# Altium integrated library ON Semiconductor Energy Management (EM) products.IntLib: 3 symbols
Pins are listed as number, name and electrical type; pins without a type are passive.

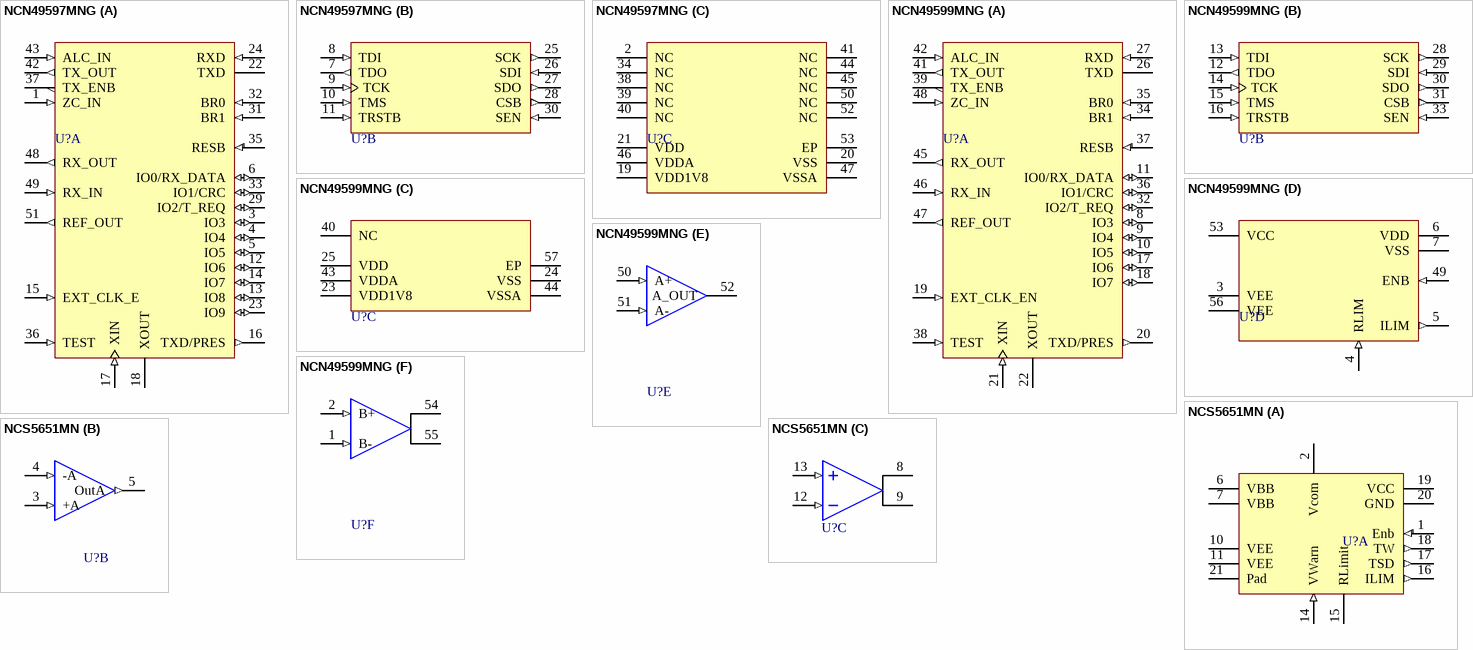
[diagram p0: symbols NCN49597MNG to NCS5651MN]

## NCN49597MNG
designator U?, comment NCN49597  (value not drawn)
Power Line Carrier Modem, 3 to 3.6 V, -40 to 115 degC, Pb-Free; Manufacturer: ON Semiconductor; PartNumber: NCN49597MNG; Data Transmission Standard: S-FSK; Number of Drivers: 1; Packing: Tube; VCC Max (V): 3.6; VCC Min (V): 3
footprint 485M_L
footprint 485M_M
footprint 485M_N
part A pins: 1 ZC_IN (in) "50/60 Hz input for mains zero cross detection", 3 IO3 (io) "General Purpose I/O’s", 4 IO4 (io) "General Purpose I/O’s", 5 IO5 (io) "General Purpose I/O’s", 6 IO0/RX_DATA (io) "Data reception indication (in ROM mode)", 12 IO6 (io) "General Purpose I/O’s", 13 IO8 (io) "General Purpose I/O’s", 14 IO7 (io) "General Purpose I/O’s", 15 EXT_CLK_E (in) "External Clock Enable input", 16 TXD/PRES (out) "Output of transmitted data (TXD) or PRE_SLOT signal (PRES)", 17 XIN (in) "Xtal input (can be driven by an internal clock)", 18 XOUT "Xtal output (output floating when XIN driven by external clock)", 22 TXD (oc) "SCI transmit output", 23 IO9 (io) "General Purpose I/O’s", 24 RXD (in) "SCI receive input (Schmitt trigger input)", 29 IO2/T_REQ (io) "Transmit Request input (in ROM mode)", 31 BR1 (in) "SCI baud rate selection", 32 BR0 (in) "SCI baud rate selection", 33 IO1/CRC (io) "Correct frame CRC indication (in ROM mode)", 35 RESB (in) "Master reset bar (Schmitt trigger input, active low)", 36 TEST (in) "Hardware Test enable (Schmitt trigger input)", 37 TX_ENB (oc) "TX enable (active low)", 42 TX_OUT (out) "Transmitter output", 43 ALC_IN (in) "Automatic level control input", 48 RX_OUT (out) "Output of receiver low noise operational amplifier", 49 RX_IN (in) "Positive input of receiver low noise operational amplifier", 51 REF_OUT (out) "Reference output for stabilization"
part B pins: 7 TDO (out) "Test data output", 8 TDI (in) "Test data input", 9 TCK (in) "Test clock", 10 TMS (in) "Test mode select", 11 TRSTB (in) "Test reset bar (active low)", 25 SCK (out) "SPI interface external Flash", 26 SDI (in) "SPI interface external Flash (Schmitt trigger input)", 27 SDO (out) "SPI interface external Flash", 28 CSB (out) "SPI interface external Flash (Schmitt trigger input)", 30 SEN (in) "SPI interface Enable external Flash"
part C pins: 2 NC "Pins 2, 34, 38..41, 44, 45, 50, 52 are not connected. These pins need to be left open or connected to the GND plane.", 19 VDD1V8 (power) "1V8 regulator output. Foresee a decoupling capacitor", 20 VSS (power) "Digital ground", 21 VDD (power) "3.3V digital supply", 34 NC "Pins 2, 34, 38..41, 44, 45, 50, 52 are not connected. These pins need to be left open or connected to the GND plane.", 38 NC "Pins 2, 34, 38..41, 44, 45, 50, 52 are not connected. These pins need to be left open or connected to the GND plane.", 39 NC "Pins 2, 34, 38..41, 44, 45, 50, 52 are not connected. These pins need to be left open or connected to the GND plane.", 40 NC "Pins 2, 34, 38..41, 44, 45, 50, 52 are not connected. These pins need to be left open or connected to the GND plane.", 41 NC "Pins 2, 34, 38..41, 44, 45, 50, 52 are not connected. These pins need to be left open or connected to the GND plane.", 44 NC "Pins 2, 34, 38..41, 44, 45, 50, 52 are not connected. These pins need to be left open or connected to the GND plane.", 45 NC "Pins 2, 34, 38..41, 44, 45, 50, 52 are not connected. These pins need to be left open or connected to the GND plane.", 46 VDDA (power) "3.3V analog supply", 47 VSSA (power) "Analog ground", 50 NC "Pins 2, 34, 38..41, 44, 45, 50, 52 are not connected. These pins need to be left open or connected to the GND plane.", 52 NC "Pins 2, 34, 38..41, 44, 45, 50, 52 are not connected. These pins need to be left open or connected to the GND plane.", 53 EP

## NCN49599MNG
designator U?, comment NCN49599  (value not drawn)
Power Line Carrier Modem, 3 to 3.6 V, -40 to 85 degC, Pb-Free; Manufacturer: ON Semiconductor; PartNumber: NCN49599MNG; Data Transmission Standard: S-FSK; Number of Drivers: 1; Packing: Tube
footprint 485CN_N
footprint 485CN_L
footprint 485CN_M
part A pins: 8 IO3 (io) "General Purpose I/O?", 9 IO4 (io) "General Purpose I/O?", 10 IO5 (io) "General Purpose I/O?", 11 IO0/RX_DATA (io) "General Purpose I/O?", 17 IO6 (io) "General Purpose I/O?", 18 IO7 (io) "General Purpose I/O?", 19 EXT_CLK_EN (in) "External Clock Enable input", 20 TXD/PRES (out) "Output of transmitted data (TXD) or PRE_SLOT signal (PRES)", 21 XIN (in) "Xtal input (can be driven by an external clock)", 22 XOUT "Xtal output (output floating when XIN driven by external (clock)", 26 TXD (oc) "SCI transmit output", 27 RXD (in) "SCI receive input (Schmitt trigger input)", 32 IO2/T_REQ (io) "General Purpose I/O?", 34 BR1 (in) "SCI baud rate selection", 35 BR0 (in) "SCI baud rate selection", 36 IO1/CRC (io) "General Purpose I/O?", 37 RESB (in) "Master reset bar (Schmitt trigger input, active low)", 38 TEST (in) "Hardware Test enable (Schmitt trigger input)", 39 TX_ENB (oc) "TX enable (active low)", 41 TX_OUT (out) "Transmitter output", 42 ALC_IN (in) "Automatic level control input", 45 RX_OUT (out) "Output of receiver low noise operational amplifier", 46 RX_IN (in) "Positive input of receiver low noise operational amplifier", 47 REF_OUT (out) "Reference output for stabilization", 48 ZC_IN (in) "50/60 Hz input for mains zero cross detection"
part B pins: 12 TDO (out) "Test data output", 13 TDI (in) "Test data input", 14 TCK (in) "Test clock", 15 TMS (in) "Test mode select", 16 TRSTB (in) "Test reset bar (active low)", 28 SCK (out) "SPI interface external Flash", 29 SDI (in) "SPI interface external Flash (Schmitt trigger input)", 30 SDO (out) "SPI interface external Flash", 31 CSB (out) "SPI interface external Flash (Schmitt trigger input)", 33 SEN (in) "SPI interface Enable external Flash"
part C pins: 23 VDD1V8 (power) "1V8 regulator output. Foresee a decoupling capacitor", 24 VSS (power) "Digital ground", 25 VDD (power) "3.3V digital supply", 40 NC "Not connected pin. Tie to GND.", 43 VDDA (power) "3.3V analog supply", 44 VSSA (power) "Analog ground", 57 EP
part D pins: 3 VEE (power) "Negative supply for power amplifiers A and B", 4 RLIM (in) "Output B current limit set resistor", 5 ILIM (out) "Current limit logic flag", 6 VDD (power) "3.3V digital supply", 7 VSS (power) "Digital ground", 49 ENB (in) "Enable / shutdown power amplifier (active low)", 53 VCC (power) "Positive supply for power amplifiers A and B", 56 VEE (power) "Negative supply for power amplifiers A and B"
part E pins: 50 A+ (in) "Positive (+) input of operational amplifier A", 51 A- (in) "Negative (-) input of operational amplifier A", 52 A_OUT (hiz) "Output of operational amplifier A"
part F pins: 1 B- (in) "Negative (-) input of operational amplifier B", 2 B+ (in) "Positive (+) input of operational amplifier B", 54 B_OUT1 (hiz) "Output of operational amplifier B", 55 B_OUT2 (hiz) "Output of operational amplifier B"

## NCS5651MN
designator U?, comment NCS5651  (value not drawn)
2 amp PLC line driver; Manufacturer: ON Semiconductor; Part: NCS5651MN
footprint 485E-01-L
footprint 485E-01-M
footprint 485E-01-N
part A pins: 1 Enb (in), 2 Vcom (power), 6 VBB (power), 7 VBB (power), 10 VEE (power), 11 VEE (power), 14 VWarn (in), 15 RLimit, 16 ILIM (out), 17 TSD (out), 18 TW (out), 19 VCC (power), 20 GND (power), 21 Pad (power)
part B pins: 3 +A (in), 4 -A (in), 5 OutA (out)
part C pins: 8 OutB (hiz), 9 OutB (hiz), 12 -B (in), 13 +B (in)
